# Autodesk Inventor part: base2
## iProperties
Author: Administrator
Created: 2001-09
Part Number: base2
Document SubType Name: Modeling
Designer: Administrator
Control State: 0
Master: False
Checked Out: False
PropertySet Name: Design Tracking Control
Length Units: 11272
Angle Units: 11279
Time Units: 11290
Mass Units: 11286
Shininess: 3
Angle Display Precision: 2
Document Length Units: 11272
Document Angle Units: 11286
Document Time Units: 11279
Document Mass Units: 11290
Document Length Units Precision: 3
Document Angle Units Precision: 2
Compacted: False
PropertySet Name: _Private Model Information
Density: 0.0
Volumn: 0.0
Area: 0.0
PropertySet Name: Model Information
